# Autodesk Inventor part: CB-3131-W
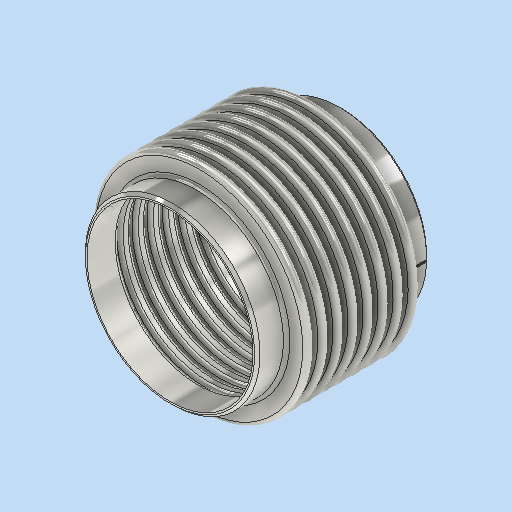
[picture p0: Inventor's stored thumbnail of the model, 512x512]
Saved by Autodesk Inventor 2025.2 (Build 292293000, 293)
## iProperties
Company: DN.RU
Created: 2026-04
Part Number: CB-3131-W
Material: Типовые
Document SubType Name: Modeling
Designer: DN.RU
Density: 3.18993 g/cm^3
Appearance: По умолчанию
Description: D140-02129
Mass: 13800 g
Surface Area: 18759.7 cm^2
Volume: 4326.11 cm^3
Author: DN.RU
Title: Компенсатор сильфонный осевой DN.ru Ду300 Ру16
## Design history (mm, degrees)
sketch "Эскиз1"
  geometry: L1 (0, 0)-(0, -160); L2 (162.5, -160)-(162.5, 0); L3 (162.5, 0)-(0, 0); L4 (162.5, 0)-(162.5, -14); L5 (132.5, -14)-(192.5, -14); L6 (132.5, -21.5)-(192.5, -21.5); L7 (192.5, -6.5)-(132.5, -6.5); L8 (192.5, -17.5)-(132.5, -17.5); L9 (132.5, -10.5)-(192.5, -10.5); L10 (192.5, -34.5)-(132.5, -34.5); L11 (132.5, -38.5)-(192.5, -38.5); L12 (132.5, -42)-(192.5, -42); L13 (132.5, -49.5)-(192.5, -49.5); L14 (192.5, -45.5)-(132.5, -45.5); L15 (192.5, -62.5)-(132.5, -62.5); L16 (132.5, -66.5)-(192.5, -66.5); L17 (132.5, -70)-(192.5, -70); L18 (132.5, -77.5)-(192.5, -77.5); L19 (192.5, -73.5)-(132.5, -73.5); L20 (192.5, -90.5)-(132.5, -90.5); L21 (132.5, -94.5)-(192.5, -94.5); L22 (132.5, -98)-(192.5, -98); L23 (132.5, -105.5)-(192.5, -105.5); L24 (192.5, -101.5)-(132.5, -101.5); L25 (0, -160)-(162.5, -160); L26 (162.5, -160)-(154.5, -160); L27 (162.5, -90.5)-(158.5, -90.5); L28 (154.5, -160)-(154.5, -101.5); L29 (162.5, -94.5)-(158.5, -94.5); L30 (158.5, -94.5)-(158.5, -73.5); L31 (162.5, -66.5)-(158.5, -66.5); L32 (158.5, -66.5)-(158.5, -45.5); L33 (162.5, -38.5)-(158.5, -38.5); L34 (158.5, -38.5)-(158.5, -17.5); L35 (162.5, -10.5)-(158.5, -10.5); L36 (158.5, -10.5)-(158.5, 0); A1 r 7.5 centre (132.5, -14) between (132.5, -6.5) and (132.5, -21.5); A2 r 7.5 centre (192.5, -14) between (192.5, -21.5) and (192.5, -6.5); A3 r 3.5 centre (132.5, -14) between (132.5, -10.5) and (132.5, -17.5); A4 r 3.5 centre (192.5, -14) between (192.5, -17.5) and (192.5, -10.5); A5 r 3.5 centre (132.5, -42) between (132.5, -38.5) and (132.5, -45.5); A6 r 7.5 centre (132.5, -42) between (132.5, -34.5) and (132.5, -49.5); A7 r 3.5 centre (192.5, -42) between (192.5, -45.5) and (192.5, -38.5); A8 r 7.5 centre (192.5, -42) between (192.5, -49.5) and (192.5, -34.5); A9 r 3.5 centre (132.5, -70) between (132.5, -66.5) and (132.5, -73.5); A10 r 7.5 centre (132.5, -70) between (132.5, -62.5) and (132.5, -77.5); A11 r 3.5 centre (192.5, -70) between (192.5, -73.5) and (192.5, -66.5); A12 r 7.5 centre (192.5, -70) between (192.5, -77.5) and (192.5, -62.5); A13 r 3.5 centre (132.5, -98) between (132.5, -94.5) and (132.5, -101.5); A14 r 7.5 centre (132.5, -98) between (132.5, -90.5) and (132.5, -105.5); A15 r 3.5 centre (192.5, -98) between (192.5, -101.5) and (192.5, -94.5); A16 r 7.5 centre (192.5, -98) between (192.5, -105.5) and (192.5, -90.5); 18 further points
  constraints: 80 end point, 32 point on circle, 16 centre point, 15 point on line, 6 midpoint, 5 perpendicular, 4 tangent, 3 parallel, 2 vertical, 1 horizontal, 69 other
  dimensions: "d0" = 160 distance of L1.start L1.end; "d1" = 162.5 distance of L2.start L1.end; "d3" = 14 distance of L2.end L4.end; "d4" = 30 distance of L4.end L5.end; "d5" = 15 diameter of A2; "d6" = 4 distance between parallel lines of L6 L8; "d9" = 28 distance of L4.end point (162.5, -42); "d14" = 8 distance of L2.start L26.end; "d15" = 4 distance of L27.start L27.end; "d16" = 4 distance of L29.start L29.end; "d17" = 4 distance of L31.start L31.end; "d18" = 4 distance of L33.start L33.end; "d19" = 4 distance of L35.start L35.end
revolve "Вращение1" sketch "Эскиз1" stored, may be unused: angle "d20" = 360 deg
mirror "Зеркальное отражение1"
chamfer "Фаска1" distance "d21" = 5; stored, may be unused: second distance "d22" = 2, angle "d23" = 45 deg
fillet "Сопряжение1" dims "d24" = 6
node "РабПлоскость1"
sketch "Эскиз2"
  geometry: L1 (6.86, 17.839)-(6.86, -22.552); L2 (6.86, -22.552)-(-1.271, -22.552); L3 (-1.271, -22.552)-(-1.271, 17.839); L4 (-1.271, 17.839)-(6.86, 17.839); 1 further point
  constraints: 2 other
feature "Рельеф1" sketch "Эскиз2" dims "d25" = 0.1, "d26" = 0
node "Твердое тело1"
node "Эскиз — прямоугольный массив1" dims "d9" = 28, "d12" = 10
